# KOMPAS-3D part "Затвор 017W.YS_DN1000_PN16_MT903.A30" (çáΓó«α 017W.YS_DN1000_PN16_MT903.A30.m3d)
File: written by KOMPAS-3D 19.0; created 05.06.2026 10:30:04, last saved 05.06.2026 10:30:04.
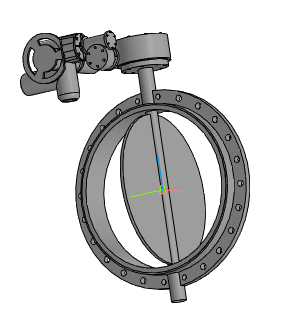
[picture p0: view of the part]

Document properties: Автор: Энергия; Полное имя файла: ..\..\..\3d для проектировщиков\x.x Тип 017W.Y(S) Затвор дисковый поворотный межфланцевый\Затвор 017W.Y(S)_DN32-DN1200_QT.A_MT903.A\Затвор 017W.YS_DN1000_PN16_MT903.A30.a3d

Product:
- Part/product: Затвор 017W.YS_DN1000_PN16_MT903.A30
    Масса: 832.26

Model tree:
1. Операция без истории:1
